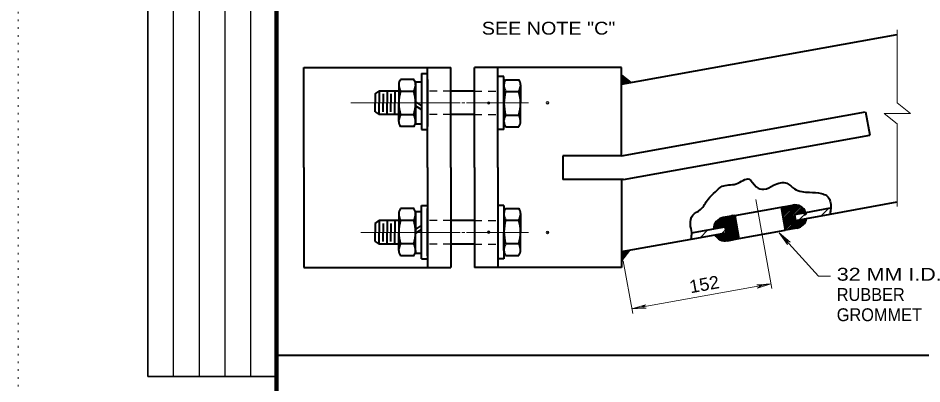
# Model space of a CAD drawing. Extents: x 312583 to 312854, y 144419 to 144597.
# Drawn here: x 312601.2 to 312654.7, y 144456.5 to 144478.1 of the extents above; entities that cross this region are included whole.
import ezdxf

# ---------------------------------------------------------------- set-up
doc = ezdxf.new("R2010")
doc.units = 0
doc.header["$LTSCALE"] = 0.3
doc.header["$PDMODE"] = 32
doc.header["$PDSIZE"] = 0.15
doc.linetypes.add('DOTTED', pattern=[1.5, 0.3, -1.2])
doc.linetypes.add('SHORT_DASHED', pattern=[2.7, 1.5, -1.2])
doc.layers.add('1', color=7, linetype='Continuous', lineweight=13)
doc.layers.add('62', color=7, linetype='DOTTED', lineweight=13)

msp = doc.modelspace()

# ---------------------------------------------------------------- linework, layer by layer
at = {"layer": '1', "lineweight": 25}
for p, q in [((312610.4087, 144456.901), (312610.4087, 144488.1192)), ((312611.9315, 144456.901), (312611.9315, 144488.1192)), ((312613.4543, 144456.901), (312613.4543, 144488.1192)), ((312614.9772, 144456.901), (312614.9772, 144488.1192)), ((312636.9323, 144474.6791), (312636.963, 144474.7174)), ((312636.9323, 144474.5948), (312637.0166, 144474.6714)), ((312636.9323, 144474.4951), (312637.0626, 144474.6331)), ((312636.9323, 144474.4108), (312637.1163, 144474.5948)), ((312636.9323, 144474.3188), (312637.1623, 144474.5564)), ((312636.9323, 144474.2268), (312637.216, 144474.5104)), ((312637.0166, 144474.2191), (312637.2696, 144474.4721)), ((312637.1316, 144474.2421), (312637.3156, 144474.4338)), ((312637.239, 144474.2651), (312637.3693, 144474.3878)), ((312637.3463, 144474.2804), (312637.4153, 144474.3494)), ((312636.9323, 144463.9764), (312637.3156, 144464.3598)), ((312636.9323, 144464.0684), (312637.2083, 144464.3444)), ((312636.9323, 144464.1604), (312637.0933, 144464.3214)), ((312636.9323, 144464.2524), (312636.986, 144464.3061)), ((312636.9323, 144463.8844), (312637.308, 144464.2601)), ((312636.9323, 144463.8001), (312637.009, 144463.8768))]:
    msp.add_line(p, q, dxfattribs=at)
at = {"layer": '1', "lineweight": 40}
for p, q in [((312636.9323, 144474.2038), (312653.2546, 144477.1401)), ((312618.1106, 144469.2588), (312618.1106, 144475.1851)), ((312625.4323, 144469.2588), (312625.4323, 144475.1851)), ((312626.82, 144469.2588), (312626.82, 144475.1851)), ((312628.2153, 144469.2588), (312628.2153, 144475.1851)), ((312629.6106, 144469.2588), (312629.6106, 144475.1851)), ((312636.9323, 144469.9564), (312636.9323, 144475.1851)), ((312624.6426, 144474.4798), (312623.8453, 144474.4798)), ((312625.0796, 144474.8248), (312625.0796, 144471.5204)), ((312625.0796, 144474.8248), (312625.4323, 144474.8248)), ((312625.4323, 144474.4798), (312625.4323, 144471.6891)), ((312629.9556, 144474.6561), (312629.6106, 144474.6561)), ((312629.6106, 144471.6891), (312629.6106, 144474.4798)), ((312629.9556, 144471.5204), (312629.9556, 144474.6561)), ((312630.0476, 144474.4644), (312630.845, 144474.4644)), ((312636.9323, 144474.7404), (312637.4766, 144474.3034)), ((312623.7456, 144474.1654), (312623.7456, 144473.0921)), ((312624.7346, 144474.1731), (312624.7346, 144474.3341)), ((312624.7346, 144474.3341), (312624.7346, 144471.8578)), ((312624.7346, 144474.3341), (312625.0796, 144474.3341)), ((312624.7346, 144474.1731), (312624.7346, 144473.0998)), ((312629.9556, 144474.1578), (312629.9556, 144473.0844)), ((312630.9523, 144474.1578), (312630.9523, 144473.0768)), ((312622.3426, 144473.6288), (312622.3426, 144473.0921)), ((312623.7456, 144473.7898), (312622.5803, 144473.7898)), ((312622.8103, 144473.6288), (312622.8103, 144473.0921)), ((312623.048, 144473.7898), (312623.048, 144473.0921)), ((312623.278, 144473.6288), (312623.278, 144473.0921)), ((312623.508, 144473.7898), (312623.508, 144473.0921)), ((312624.6426, 144473.7744), (312623.8453, 144473.7744)), ((312628.2153, 144473.7898), (312626.82, 144473.7898)), ((312630.0476, 144473.7591), (312630.845, 144473.7591)), ((312622.3426, 144472.5631), (312622.3426, 144473.0998)), ((312622.8103, 144472.5631), (312622.8103, 144473.0998)), ((312623.048, 144472.3944), (312623.048, 144473.0998)), ((312623.278, 144472.5631), (312623.278, 144473.0998)), ((312623.508, 144472.3944), (312623.508, 144473.0998)), ((312623.7456, 144471.9958), (312623.7456, 144473.0998)), ((312624.7346, 144473.1534), (312625.0796, 144472.9234)), ((312624.7346, 144471.9958), (312624.7346, 144473.0998)), ((312624.7346, 144472.9234), (312625.0796, 144472.6934)), ((312629.9556, 144471.9804), (312629.9556, 144473.0844)), ((312630.9523, 144471.9804), (312630.9523, 144473.0844)), ((312623.7456, 144472.3944), (312622.5803, 144472.3944)), ((312624.635, 144472.3868), (312623.8376, 144472.3868)), ((312628.2153, 144472.3944), (312626.82, 144472.3944)), ((312630.0553, 144472.3714), (312630.8526, 144472.3714)), ((312636.9323, 144469.9564), (312651.3763, 144472.5554)), ((312651.3763, 144472.5554), (312651.6216, 144471.1831)), ((312624.7346, 144471.8578), (312624.7346, 144471.9958)), ((312624.7346, 144471.8578), (312625.0796, 144471.8578)), ((312624.6426, 144471.6891), (312623.8453, 144471.6891)), ((312625.0796, 144471.5204), (312625.4323, 144471.5204)), ((312629.9556, 144471.5204), (312629.6106, 144471.5204)), ((312630.0476, 144471.6738), (312630.845, 144471.6738)), ((312637.0473, 144468.5611), (312651.6216, 144471.1831)), ((312636.9323, 144469.9564), (312633.444, 144469.9564)), ((312633.444, 144469.9564), (312633.444, 144468.5611)), ((312618.1106, 144469.2588), (312618.1106, 144463.3401)), ((312625.4323, 144469.2588), (312625.4323, 144463.3401)), ((312626.82, 144469.2588), (312626.82, 144463.3401)), ((312628.2153, 144469.2588), (312628.2153, 144463.3401)), ((312629.6106, 144469.2588), (312629.6106, 144463.3401)), ((312637.0473, 144468.5611), (312633.444, 144468.5611)), ((312636.9323, 144468.5611), (312636.9323, 144463.3401)), ((312625.0796, 144463.8691), (312625.0796, 144467.0124)), ((312625.0796, 144467.0124), (312625.4323, 144467.0124)), ((312629.9556, 144467.0124), (312629.6106, 144467.0124)), ((312629.9556, 144467.0124), (312629.9556, 144463.8691)), ((312643.633, 144466.4298), (312646.3776, 144466.9204)), ((312646.3776, 144466.9204), (312647.06, 144467.0431)), ((312646.3776, 144466.9204), (312646.623, 144465.5558)), ((312649.2756, 144466.5141), (312653.2546, 144467.2271)), ((312623.7456, 144466.5294), (312623.7456, 144465.4254)), ((312624.6426, 144466.8361), (312623.8453, 144466.8361)), ((312624.7346, 144466.6674), (312624.7346, 144466.5294)), ((312624.7346, 144466.6674), (312625.0796, 144466.6674)), ((312624.7346, 144464.1911), (312624.7346, 144466.6674)), ((312624.7346, 144466.5294), (312624.7346, 144465.4254)), ((312625.4323, 144464.0454), (312625.4323, 144466.8361)), ((312629.6106, 144466.8361), (312629.6106, 144464.0454)), ((312629.9556, 144466.5448), (312629.9556, 144465.4408)), ((312630.0476, 144466.8438), (312630.845, 144466.8438)), ((312630.9523, 144466.5371), (312630.9523, 144465.4331)), ((312643.633, 144466.4298), (312642.9506, 144466.3071)), ((312643.633, 144466.4298), (312643.8783, 144465.0574)), ((312647.1596, 144466.4911), (312647.8343, 144466.6138)), ((312647.1596, 144466.4911), (312647.2286, 144466.1384)), ((312647.2286, 144466.1384), (312649.2756, 144466.5141)), ((312647.8343, 144466.6138), (312649.3063, 144466.8744)), ((312622.3426, 144465.9621), (312622.3426, 144465.4254)), ((312623.7456, 144466.1231), (312622.5803, 144466.1231)), ((312622.8103, 144465.9621), (312622.8103, 144465.4254)), ((312623.048, 144466.1231), (312623.048, 144465.4254)), ((312623.278, 144465.9621), (312623.278, 144465.4254)), ((312623.508, 144466.1231), (312623.508, 144465.4254)), ((312624.635, 144466.1384), (312623.8376, 144466.1384)), ((312628.2153, 144466.1231), (312626.82, 144466.1231)), ((312630.0553, 144466.1538), (312630.8526, 144466.1538)), ((312622.3426, 144464.8964), (312622.3426, 144465.4331)), ((312622.8103, 144464.8964), (312622.8103, 144465.4331)), ((312623.048, 144464.7278), (312623.048, 144465.4331)), ((312623.278, 144464.8964), (312623.278, 144465.4331)), ((312623.508, 144464.7278), (312623.508, 144465.4331)), ((312623.7456, 144464.3521), (312623.7456, 144465.4331)), ((312624.7346, 144465.6018), (312625.0796, 144465.8318)), ((312624.7346, 144465.3718), (312625.0796, 144465.6018)), ((312624.7346, 144464.3521), (312624.7346, 144465.4254)), ((312629.9556, 144464.3598), (312629.9556, 144465.4408)), ((312630.9523, 144464.3674), (312630.9523, 144465.4484)), ((312641.0493, 144465.0344), (312643.1116, 144465.4024)), ((312641.0723, 144465.3948), (312643.0503, 144465.7474)), ((312643.0503, 144465.7474), (312643.1116, 144465.4024)), ((312643.8783, 144465.0574), (312646.623, 144465.5558)), ((312647.3053, 144465.6784), (312646.623, 144465.5558)), ((312636.9323, 144464.2984), (312641.0493, 144465.0344)), ((312643.196, 144464.9348), (312643.8783, 144465.0574)), ((312623.7456, 144464.7278), (312622.5803, 144464.7278)), ((312624.6426, 144464.7508), (312623.8453, 144464.7508)), ((312624.7346, 144464.3521), (312624.7346, 144464.1911)), ((312628.2153, 144464.7278), (312626.82, 144464.7278)), ((312630.0476, 144464.7661), (312630.845, 144464.7661)), ((312636.9323, 144463.7694), (312637.4, 144464.3828)), ((312624.6426, 144464.0454), (312623.8453, 144464.0454)), ((312624.7346, 144464.1911), (312625.0796, 144464.1911)), ((312625.0796, 144463.8691), (312625.4323, 144463.8691)), ((312629.9556, 144463.8691), (312629.6106, 144463.8691)), ((312630.0476, 144464.0608), (312630.845, 144464.0608)), ((312801.9986, 144458.1429), (312616.5, 144458.1429))]:
    msp.add_line(p, q, dxfattribs=at)
at = {"layer": '1'}
for p, q in [((312653.2546, 144477.4161), (312653.2546, 144473.0844)), ((312627.3643, 144473.0921), (312620.909, 144473.0921)), ((312627.4716, 144473.0921), (312627.6403, 144473.0921)), ((312627.7476, 144473.0921), (312631.42, 144473.0921)), ((312653.2546, 144471.8424), (312653.2546, 144466.9511)), ((312644.875, 144467.3804), (312645.8256, 144462.1058)), ((312647.4663, 144466.1844), (312647.911, 144466.6214)), ((312648.7466, 144466.4144), (312649.1913, 144466.8591)), ((312627.3643, 144465.4254), (312621.4916, 144465.4254)), ((312627.4716, 144465.4254), (312627.6403, 144465.4254)), ((312627.7476, 144465.4254), (312631.42, 144465.4254)), ((312641.5936, 144465.1341), (312642.023, 144465.5634)), ((312642.874, 144465.3641), (312643.081, 144465.5711)), ((312646.2651, 144465.4063), (312646.7481, 144464.7163)), ((312646.2651, 144465.4063), (312646.9014, 144464.8543)), ((312646.7481, 144464.7163), (312646.6484, 144464.9846)), ((312646.9014, 144464.8543), (312646.6484, 144464.9846)), ((312637.0243, 144463.7464), (312637.5916, 144460.6184)), ((312637.538, 144460.8944), (312645.772, 144462.3818)), ((312645.772, 144462.3818), (312644.9286, 144462.3281)), ((312644.9286, 144462.3281), (312645.2123, 144462.2744)), ((312645.772, 144462.3818), (312644.967, 144462.1288)), ((312644.967, 144462.1288), (312645.2123, 144462.2744)), ((312637.538, 144460.8944), (312638.3506, 144461.1474)), ((312638.3506, 144461.1474), (312638.1053, 144460.9941)), ((312637.538, 144460.8944), (312638.3813, 144460.9404)), ((312638.3813, 144460.9404), (312638.1053, 144460.9941))]:
    msp.add_line(p, q, dxfattribs=at)
at = {"layer": '1', "linetype": 'SHORT_DASHED', "lineweight": 25}
for p, q in [((312626.82, 144473.7898), (312625.4323, 144473.7898)), ((312628.2153, 144473.7898), (312629.6106, 144473.7898)), ((312626.82, 144472.3944), (312625.4323, 144472.3944)), ((312628.2153, 144472.3944), (312629.6106, 144472.3944)), ((312626.82, 144466.1231), (312625.4323, 144466.1231)), ((312628.2153, 144466.1231), (312629.6106, 144466.1231)), ((312626.82, 144464.7278), (312625.4323, 144464.7278)), ((312628.2153, 144464.7278), (312629.6106, 144464.7278))]:
    msp.add_line(p, q, dxfattribs=at)
at = {"layer": '1', "lineweight": 35}
for p, q in [((312646.3853, 144466.8744), (312646.4466, 144466.9358)), ((312646.4006, 144466.7978), (312646.5616, 144466.9511)), ((312646.416, 144466.7134), (312646.669, 144466.9741)), ((312646.4236, 144466.6444), (312646.784, 144466.9894)), ((312646.439, 144466.5601), (312646.8913, 144467.0124)), ((312646.4543, 144466.4911), (312647.0063, 144467.0354)), ((312646.4696, 144466.4068), (312647.1136, 144467.0508)), ((312646.485, 144466.3378), (312647.2056, 144467.0508)), ((312646.5003, 144466.2534), (312647.2823, 144467.0431)), ((312646.508, 144466.1768), (312647.3666, 144467.0354)), ((312646.5233, 144466.1001), (312647.428, 144467.0124)), ((312646.5386, 144466.0234), (312647.4893, 144466.9818)), ((312646.554, 144465.9468), (312647.5506, 144466.9511)), ((312642.6823, 144465.6861), (312643.3876, 144466.3838)), ((312642.7973, 144465.7014), (312643.495, 144466.4068)), ((312642.9123, 144465.7244), (312643.6023, 144466.4221)), ((312646.5693, 144465.8701), (312647.1673, 144466.4681)), ((312646.577, 144465.7934), (312647.1826, 144466.3991)), ((312647.1903, 144466.4911), (312647.6043, 144466.9051)), ((312647.52, 144466.5524), (312647.7423, 144466.7748)), ((312647.6273, 144466.5678), (312647.7806, 144466.7211)), ((312647.7423, 144466.5908), (312647.8113, 144466.6598)), ((312642.3756, 144465.6401), (312643.0503, 144466.3224)), ((312642.391, 144465.7551), (312642.943, 144466.3071)), ((312642.4216, 144465.8778), (312642.7973, 144466.2534)), ((312642.4676, 144465.6478), (312643.1653, 144466.3454)), ((312642.575, 144465.6631), (312643.2726, 144466.3608)), ((312642.7436, 144465.0191), (312643.7096, 144465.9851)), ((312642.805, 144464.9884), (312643.725, 144465.9084)), ((312643.012, 144465.7398), (312643.6406, 144466.3684)), ((312643.058, 144465.6938), (312643.656, 144466.2918)), ((312643.0733, 144465.6171), (312643.6636, 144466.2151)), ((312643.0886, 144465.5404), (312643.679, 144466.1384)), ((312643.104, 144465.4638), (312643.6943, 144466.0618)), ((312646.5923, 144465.7244), (312647.1903, 144466.3148)), ((312646.6076, 144465.6401), (312647.2056, 144466.2381)), ((312646.623, 144465.5711), (312647.221, 144466.1691)), ((312646.7226, 144465.5711), (312647.3053, 144466.1538)), ((312646.83, 144465.5941), (312647.4126, 144466.1768)), ((312646.945, 144465.6171), (312647.5276, 144466.1921)), ((312647.0523, 144465.6324), (312647.635, 144466.2151)), ((312647.1596, 144465.6554), (312647.7423, 144466.2304)), ((312647.2746, 144465.6708), (312647.8573, 144466.2534)), ((312647.3973, 144465.7091), (312647.8496, 144466.1538)), ((312647.5736, 144465.7934), (312647.7653, 144465.9851)), ((312642.506, 144465.2338), (312642.5826, 144465.3104)), ((312642.5443, 144465.1801), (312642.6976, 144465.3334)), ((312642.5826, 144465.1264), (312642.805, 144465.3564)), ((312642.6363, 144465.0881), (312642.92, 144465.3718)), ((312642.6823, 144465.0498), (312643.0273, 144465.3948)), ((312642.874, 144464.9654), (312643.7403, 144465.8318)), ((312642.943, 144464.9424), (312643.7556, 144465.7551)), ((312643.0273, 144464.9348), (312643.771, 144465.6784)), ((312643.1116, 144464.9271), (312643.7786, 144465.6018)), ((312643.2113, 144464.9424), (312643.794, 144465.5251)), ((312643.3263, 144464.9654), (312643.8093, 144465.4484)), ((312643.4336, 144464.9808), (312643.8246, 144465.3718)), ((312642.46, 144465.2798), (312642.4753, 144465.2951)), ((312643.541, 144465.0038), (312643.84, 144465.2951)), ((312643.656, 144465.0191), (312643.8476, 144465.2184)), ((312643.7633, 144465.0421), (312643.863, 144465.1418)), ((312643.8706, 144465.0574), (312643.8783, 144465.0651))]:
    msp.add_line(p, q, dxfattribs=at)
at = {"layer": '1', "lineweight": 158}
msp.add_lwpolyline([(312616.5, 144423.1446), (312616.5, 144585.0846), (312849, 144585.0846)], dxfattribs=at)
at = {"layer": '1', "lineweight": 35}
for points in [[(312616.5, 144456.901), (312608.8858, 144456.901), (312608.8858, 144488.1192), (312616.5, 144488.1192)], [(312647.2976, 144466.5141), (312647.6503, 144466.8668), (312647.658, 144466.8744)], [(312647.405, 144466.5294), (312647.6963, 144466.8284), (312647.704, 144466.8284)]]:
    msp.add_lwpolyline(points, dxfattribs=at)
at = {"layer": '1', "lineweight": 40}
for points in [[(312618.1106, 144475.1851), (312625.4323, 144475.1851), (312626.82, 144475.1851)], [(312636.9323, 144475.1851), (312629.6106, 144475.1851), (312628.2153, 144475.1851)], [(312622.3426, 144473.6288), (312622.5803, 144473.7898), (312622.5803, 144473.0921)], [(312622.3426, 144472.5631), (312622.5803, 144472.3944), (312622.5803, 144473.0998)], [(312622.3426, 144465.9621), (312622.5803, 144466.1231), (312622.5803, 144465.4254)], [(312622.3426, 144464.8964), (312622.5803, 144464.7278), (312622.5803, 144465.4331)], [(312618.1106, 144463.3401), (312625.4323, 144463.3401), (312626.82, 144463.3401)], [(312636.9323, 144463.3401), (312629.6106, 144463.3401), (312628.2153, 144463.3401)]]:
    msp.add_lwpolyline(points, dxfattribs=at)
at = {"layer": '1', "lineweight": 25}
msp.add_lwpolyline([(312637.4613, 144474.3034), (312637.469, 144474.3111), (312637.469, 144474.3111)], dxfattribs=at)
at = {"layer": '1'}
for points in [[(312653.2546, 144471.8424), (312652.4803, 144472.4558), (312654.029, 144472.4558), (312653.2546, 144473.0844)], [(312646.2651, 144465.4063), (312648.5958, 144462.8303), (312649.2934, 144462.8303)]]:
    msp.add_lwpolyline(points, dxfattribs=at)
at = {"layer": '1', "lineweight": 40}
for centre, radius, start, end in [((312624.3151, 144474.1518), 0.574, 145.8703, 178.33743), ((312624.1569, 144474.1518), 0.574, 1.66257, 34.1297), ((312630.534, 144474.1379), 0.574, 145.8703, 178.33743), ((312630.3759, 144474.1379), 0.574, 1.66257, 34.1297), ((312625.3489, 144474.429), 1.6437, 191.77014, 203.36365), ((312623.1232, 144474.429), 1.6437, 336.63635, 348.22986), ((312631.5678, 144474.4151), 1.6437, 191.77014, 203.36365), ((312629.3421, 144474.4151), 1.6437, 336.63635, 348.22986), ((312626.7052, 144473.0093), 2.9664, 164.99798, 178.595), ((312621.7668, 144473.0093), 2.9664, 1.405, 15.00202), ((312632.9242, 144472.9954), 2.9664, 164.99798, 178.595), ((312627.9858, 144472.9954), 2.9664, 1.405, 15.00202), ((312626.7052, 144473.1548), 2.9664, 181.405, 195.00202), ((312621.7668, 144473.1548), 2.9664, 344.99798, 358.595), ((312632.9242, 144473.1409), 2.9664, 181.405, 195.00202), ((312627.9858, 144473.1409), 2.9664, 344.99798, 358.595), ((312625.3489, 144471.7351), 1.6437, 156.63635, 168.22986), ((312623.1232, 144471.7351), 1.6437, 11.77014, 23.36365), ((312631.5678, 144471.7212), 1.6437, 156.63635, 168.22986), ((312629.3421, 144471.7212), 1.6437, 11.77014, 23.36365), ((312624.3151, 144472.0123), 0.574, 181.66257, 214.1297), ((312624.1569, 144472.0123), 0.574, 325.8703, 358.33743), ((312630.534, 144471.9983), 0.574, 181.66257, 214.1297), ((312630.3759, 144471.9983), 0.574, 325.8703, 358.33743), ((312647.1881, 144466.3626), 0.694, 20.92751, 100.40744), ((312625.3489, 144466.788), 1.6437, 191.77014, 203.36365), ((312624.3151, 144466.5108), 0.574, 145.8703, 178.33743), ((312624.1569, 144466.5108), 0.574, 1.66257, 34.1297), ((312623.1232, 144466.788), 1.6437, 336.63635, 348.22986), ((312631.5678, 144466.8019), 1.6437, 191.77014, 203.36365), ((312630.534, 144466.5248), 0.574, 145.8703, 178.33743), ((312629.3421, 144466.8019), 1.6437, 336.63635, 348.22986), ((312630.3759, 144466.5248), 0.574, 1.66257, 34.1297), ((312626.7052, 144465.3683), 2.9664, 164.99798, 178.595), ((312621.7668, 144465.3683), 2.9664, 1.405, 15.00202), ((312632.9242, 144465.3823), 2.9664, 164.99798, 178.595), ((312627.9858, 144465.3823), 2.9664, 1.405, 15.00202), ((312643.0671, 144465.6207), 0.694, 99.90643, 179.34108), ((312647.1881, 144466.3626), 0.694, 279.9552, 351.41104), ((312626.7052, 144465.5138), 2.9664, 181.405, 195.00202), ((312621.7668, 144465.5138), 2.9664, 344.99798, 358.595), ((312632.9242, 144465.5277), 2.9664, 181.405, 195.00202), ((312627.9858, 144465.5277), 2.9664, 344.99798, 358.595), ((312643.0671, 144465.6207), 0.694, 208.60683, 280.45563), ((312625.3489, 144464.0941), 1.6437, 156.63635, 168.22986), ((312624.3151, 144464.3713), 0.574, 181.66257, 214.1297), ((312623.1232, 144464.0941), 1.6437, 11.77014, 23.36365), ((312624.1569, 144464.3713), 0.574, 325.8703, 358.33743), ((312631.5678, 144464.108), 1.6437, 156.63635, 168.22986), ((312630.534, 144464.3852), 0.574, 181.66257, 214.1297), ((312629.3421, 144464.108), 1.6437, 11.77014, 23.36365), ((312630.3759, 144464.3852), 0.574, 325.8703, 358.33743)]:
    msp.add_arc(centre, radius, start, end, dxfattribs=at)
msp.add_spline([(312641.0493, 144465.0344), (312641.08, 144465.4254), (312641.0033, 144465.8931), (312641.149, 144466.4451), (312641.6013, 144466.7748), (312642.0536, 144467.3958), (312642.483, 144467.8251), (312642.8816, 144468.1548), (312643.7096, 144468.3004), (312644.484, 144468.5764), (312644.9056, 144468.1241), (312645.358, 144467.9784), (312645.933, 144468.2238), (312646.715, 144468.3311), (312647.1596, 144468.0014), (312648.0643, 144467.8021), (312648.762, 144467.7254), (312649.061, 144467.6028), (312649.314, 144467.1044), (312649.2986, 144466.7364), (312649.2756, 144466.5141)], degree=3, dxfattribs=at)
at = {"layer": '1'}
for p in [(312629.0586, 144473.0844), (312632.547, 144473.0921), (312643.495, 144466.3991), (312643.541, 144466.3531), (312643.587, 144466.3071), (312647.8036, 144466.5294), (312643.6253, 144466.2611), (312629.0586, 144465.4408), (312632.547, 144465.4254)]:
    msp.add_point(p, dxfattribs=at)
at = {"layer": '62'}
msp.add_line((312601.2, 144418.5846), (312601.2, 144596.7846), dxfattribs=at)

# ---------------------------------------------------------------- texts
at = {"layer": '1'}
for s, width, p in [('SEE NOTE "C"', 1.15, (312628.6523, 144477.1304)), ('32 MM I.D.', 1.25, (312649.6691, 144462.5686)), ('RUBBER', 0.95, (312649.6691, 144461.3716)), ('GROMMET', 0.95, (312649.6691, 144460.1746))]:
    msp.add_text(s, height=0.76, dxfattribs=dict(at, width=width)).set_placement(p)
at = {"layer": '1', "width": 1.05}
msp.add_text('152', height=0.76, rotation=10.213, dxfattribs=at).set_placement((312641.0155, 144461.8219))

doc.saveas('drawing.dxf')
